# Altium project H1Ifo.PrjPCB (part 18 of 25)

## Sheet IfoEndX2.SchDoc: D1800185
size C; Engineer: Daniel Sigg; DocumentNumber: 6; Revision: 4; SheetNumber: 6; SheetTotal: 8
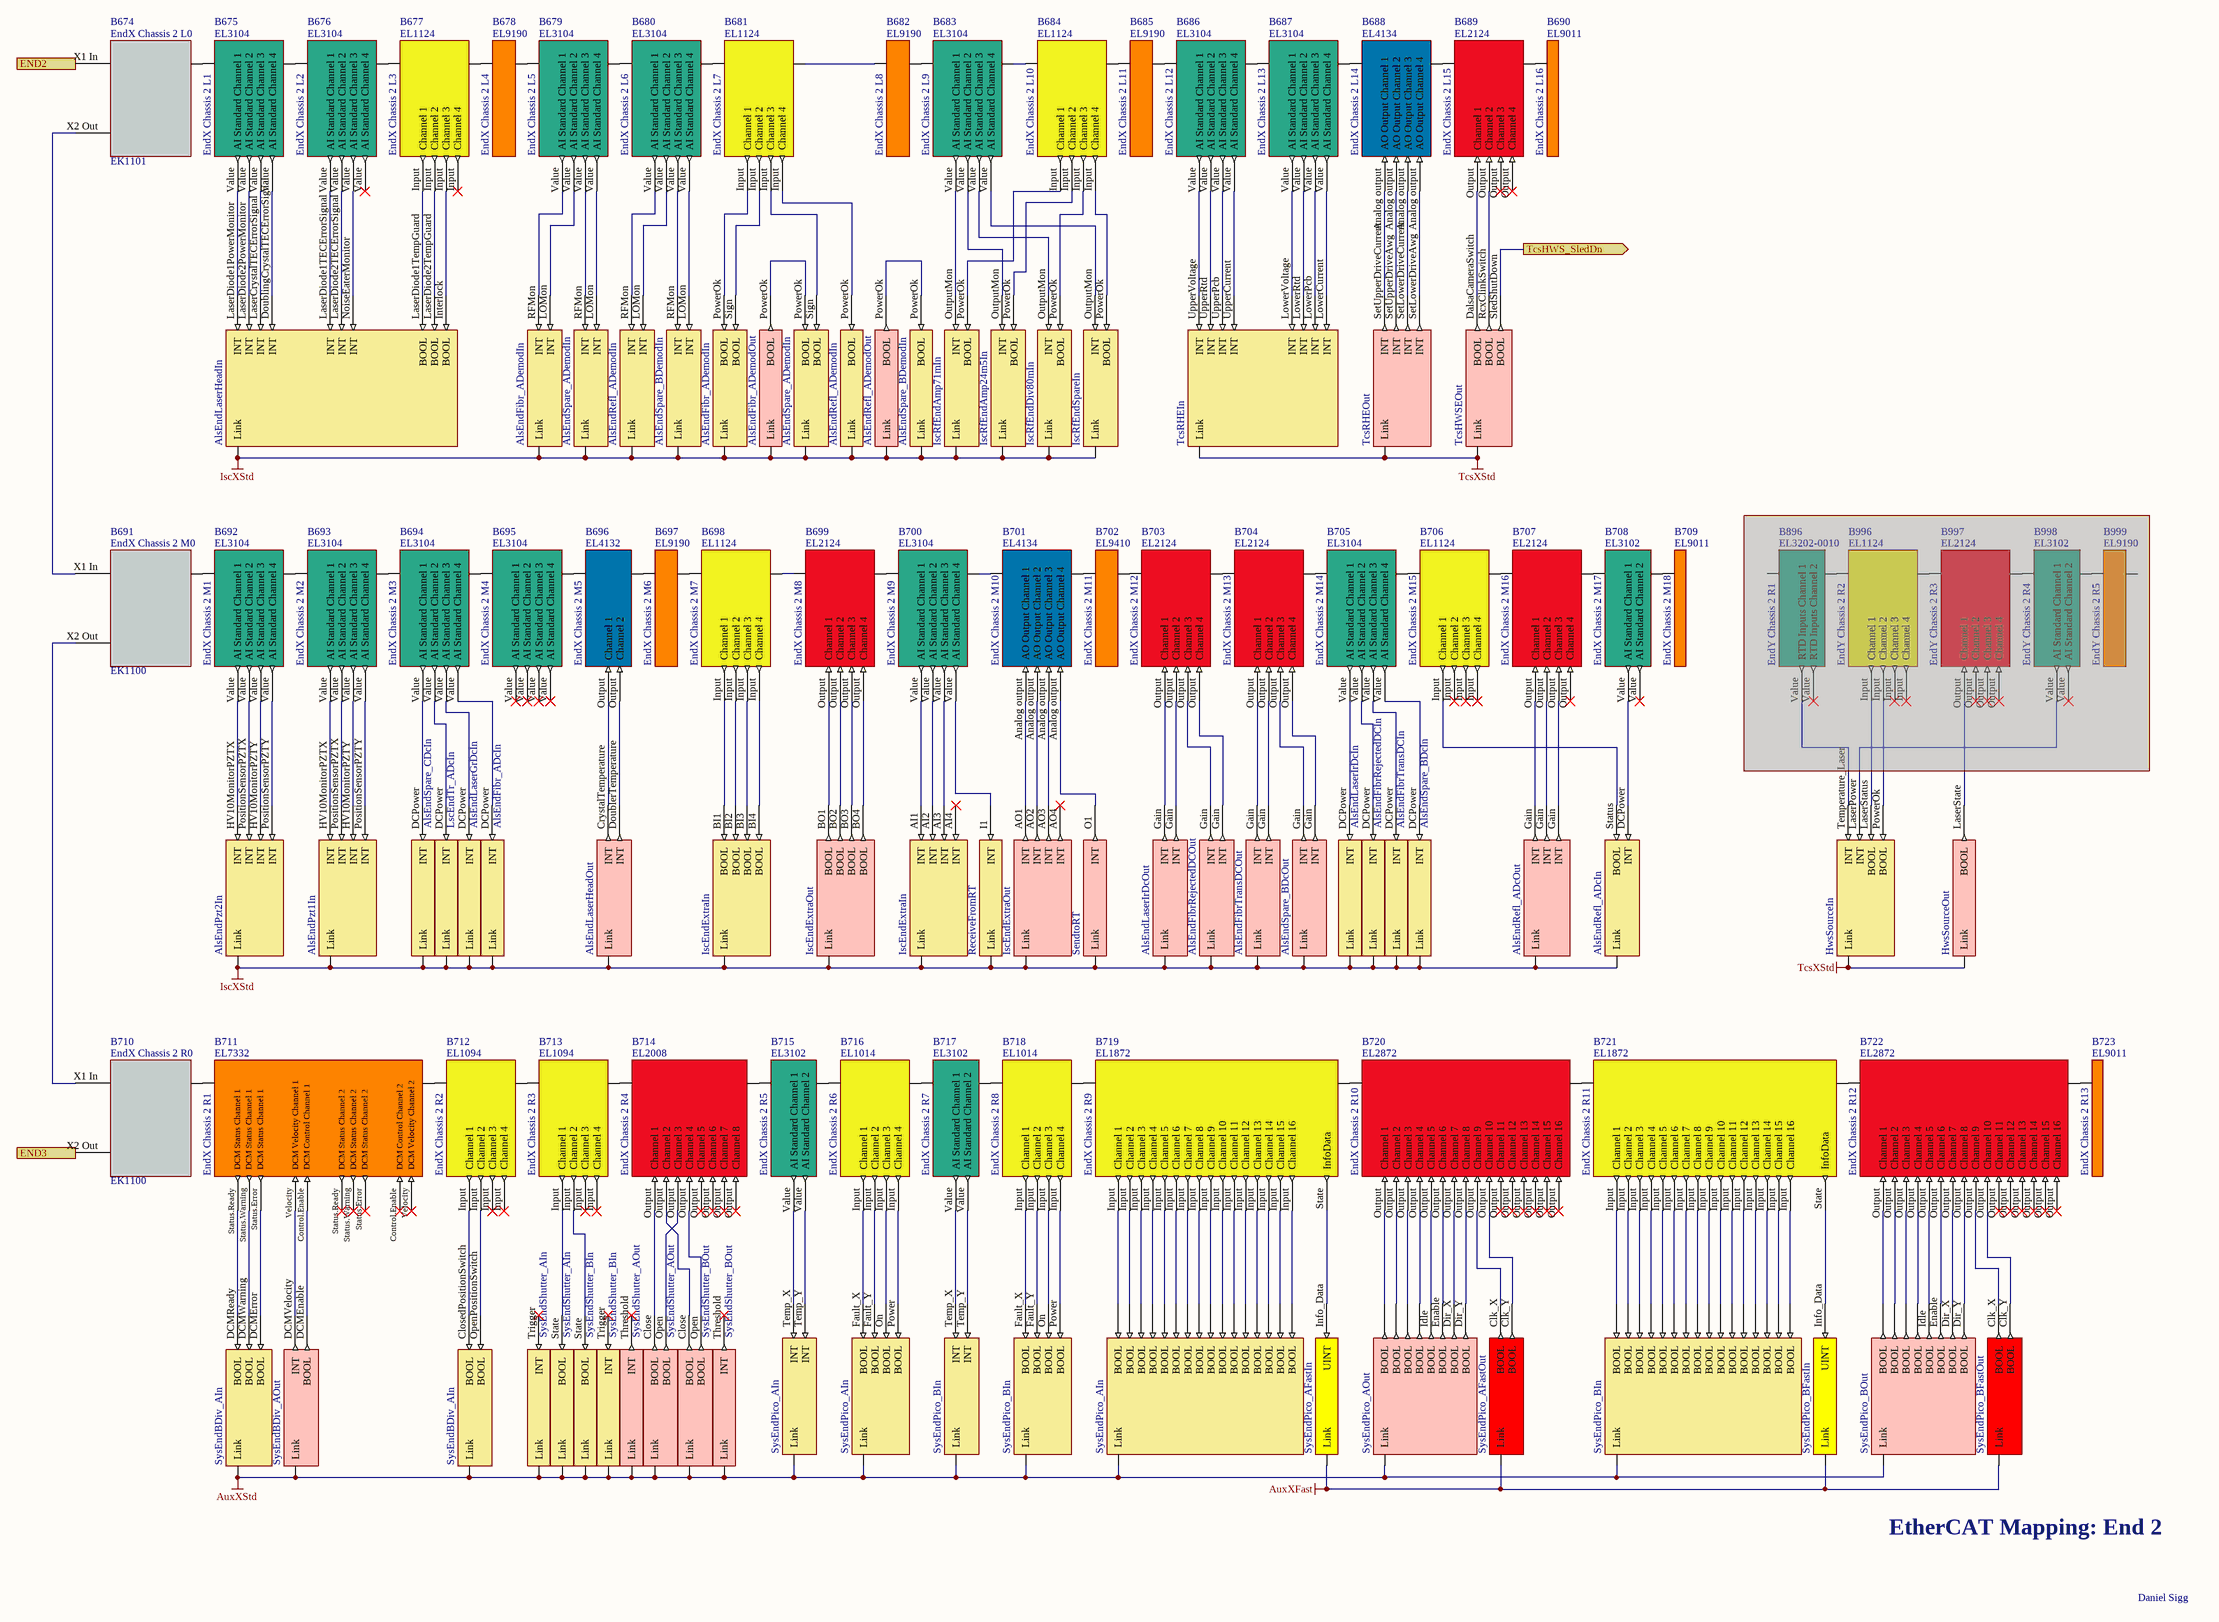
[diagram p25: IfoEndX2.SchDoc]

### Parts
(Parts that share a designator on the sheet are numbered #1, #2 ... from top to bottom, then left to right.)
B674  EndX Chassis 2 L0  Part Number: EK1101
B675  EndX Chassis 2 L1  Part Number: EL3104  (mechanical)
B676  EndX Chassis 2 L2  Part Number: EL3104  (mechanical)
B677  EndX Chassis 2 L3  Part Number: EL1124  (mechanical)
B678  EndX Chassis 2 L4  Part Number: EL9190  (mechanical)
B679  EndX Chassis 2 L5  Part Number: EL3104  (mechanical)
B680  EndX Chassis 2 L6  Part Number: EL3104  (mechanical)
B681  EndX Chassis 2 L7  Part Number: EL1124  (mechanical)
B682  EndX Chassis 2 L8  Part Number: EL9190  (mechanical)
B683  EndX Chassis 2 L9  Part Number: EL3104  (mechanical)
B684  EndX Chassis 2 L10  Part Number: EL1124  (mechanical)
B685  EndX Chassis 2 L11  Part Number: EL9190  (mechanical)
B686  EndX Chassis 2 L12  Part Number: EL3104  (mechanical)
B687  EndX Chassis 2 L13  Part Number: EL3104  (mechanical)
B688  EndX Chassis 2 L14  Part Number: EL4134  (mechanical)
B689  EndX Chassis 2 L15  Part Number: EL2124  (mechanical)
B690  EndX Chassis 2 L16  Part Number: EL9011  (mechanical)
B691  EndX Chassis 2 M0  Part Number: EK1100
B692  EndX Chassis 2 M1  Part Number: EL3104  (mechanical)
B693  EndX Chassis 2 M2  Part Number: EL3104  (mechanical)
B694  EndX Chassis 2 M3  Part Number: EL3104  (mechanical)
B695  EndX Chassis 2 M4  Part Number: EL3104  (mechanical)
B696  EndX Chassis 2 M5  Part Number: EL4132  (mechanical)
B697  EndX Chassis 2 M6  Part Number: EL9190  (mechanical)
B698  EndX Chassis 2 M7  Part Number: EL1124  (mechanical)
B699  EndX Chassis 2 M8  Part Number: EL2124  (mechanical)
B700  EndX Chassis 2 M9  Part Number: EL3104  (mechanical)
B701  EndX Chassis 2 M10  Part Number: EL4134  (mechanical)
B702  EndX Chassis 2 M11  Part Number: EL9410  (mechanical)
B703  EndX Chassis 2 M12  Part Number: EL2124  (mechanical)
B704  EndX Chassis 2 M13  Part Number: EL2124  (mechanical)
B705  EndX Chassis 2 M14  Part Number: EL3104  (mechanical)
B706  EndX Chassis 2 M15  Part Number: EL1124  (mechanical)
B707  EndX Chassis 2 M16  Part Number: EL2124  (mechanical)
B708  EndX Chassis 2 M17  Part Number: EL3102  (mechanical)
B709  EndX Chassis 2 M18  Part Number: EL9011  (mechanical)
B710  EndX Chassis 2 R0  Part Number: EK1100
B711  EndX Chassis 2 R1  Part Number: EL7332  (mechanical)
B712  EndX Chassis 2 R2  Part Number: EL1094  (mechanical)
B713  EndX Chassis 2 R3  Part Number: EL1094  (mechanical)
B714  EndX Chassis 2 R4  Part Number: EL2008  (mechanical)
B715  EndX Chassis 2 R5  Part Number: EL3102  (mechanical)
B716  EndX Chassis 2 R6  Part Number: EL1014  (mechanical)
B717  EndX Chassis 2 R7  Part Number: EL3102  (mechanical)
B718  EndX Chassis 2 R8  Part Number: EL1014  (mechanical)
B719  EndX Chassis 2 R9  Part Number: EL1872  (mechanical)
B720  EndX Chassis 2 R10  Part Number: EL2872  (mechanical)
B721  EndX Chassis 2 R11  Part Number: EL1872  (mechanical)
B722  EndX Chassis 2 R12  Part Number: EL2872  (mechanical)
B723  EndX Chassis 2 R13  Part Number: EL9011  (mechanical)
B896#1  EndY Chassis 2 R1  Part Number: EL3202-0010  (mechanical)  (masked out: inside a compile mask, not in the netlist)
B996#1  EndY Chassis 2 R2  Part Number: EL1124  (mechanical)  (masked out: inside a compile mask, not in the netlist)
B997#1  EndY Chassis 2 R3  Part Number: EL2124  (mechanical)  (masked out: inside a compile mask, not in the netlist)
B998#1  EndY Chassis 2 R4  Part Number: EL3102  (mechanical)  (masked out: inside a compile mask, not in the netlist)
B999#1  EndY Chassis 2 R5  Part Number: EL9190  (mechanical)  (masked out: inside a compile mask, not in the netlist)
V97  HwsSourceIn  (no BOM)
V98  HwsSourceOut  (no BOM)
V400  AlsEndFibr_ADemodOut  (no BOM)
V401  AlsEndRefl_ADemodOut  (no BOM)
V402  AlsEndFibr_ADemodIn  (parts A,B of 2)  (no BOM)
V403  AlsEndSpare_ADemodIn  (parts A,B of 2)  (no BOM)
V404  AlsEndRefl_ADemodIn  (parts A,B of 2)  (no BOM)
V405  AlsEndSpare_BDemodIn  (parts A,B of 2)  (no BOM)
V488  SysEndPico_AIn  (parts A,B,C of 3)  (no BOM)
V489  SysEndPico_BIn  (parts A,B,C of 3)  (no BOM)
V542  AlsEndLaserHeadIn  (no BOM)
V543  IscRfEndAmp71mIn  (no BOM)
V544  IscRfEndAmp24m5In  (no BOM)
V545  IscRfEndDiv80mIn  (no BOM)
V546  IscRfEndSpareIn  (no BOM)
V547  TcsRHEIn  (no BOM)
V548  TcsRHEOut  (no BOM)
V549  TcsHWSEOut  (no BOM)
V550  AlsEndPzt2In  (no BOM)
V551  AlsEndPzt1In  (no BOM)
V552  AlsEndSpare_CDcIn  (no BOM)
V553  LscEndTr_ADcIn  (no BOM)
V554  AlsEndLaserGrDcIn  (no BOM)
V555  AlsEndFibr_ADcIn  (no BOM)
V556  AlsEndLaserHeadOut  (part A of 2)  (no BOM)
V557  IscEndExtraIn  (parts A,B of 2)  (no BOM)
V558  IscEndExtraOut  (parts A,B of 2)  (no BOM)
V559  ReceiveFromRT  (no BOM)
V560  SendtoRT  (no BOM)
V561  AlsEndLaserIrDcOut  (no BOM)
V562  AlsEndFibrRejectedDCOut  (no BOM)
V563  AlsEndFibrTransDCOut  (no BOM)
V564  AlsEndSpare_BDcOut  (no BOM)
V565  AlsEndLaserIrDcIn  (no BOM)
V566  AlsEndFibrRejectedDCIn  (no BOM)
V569  AlsEndFibrTransDCIn  (no BOM)
V570  AlsEndSpare_BDcIn  (no BOM)
V571  AlsEndRefl_ADcOut  (no BOM)
V572  AlsEndRefl_ADcIn  (no BOM)
V573  SysEndPico_AFastIn  (no BOM)
V574  SysEndPico_AOut  (no BOM)
V575  SysEndPico_AFastOut  (no BOM)
V576  SysEndPico_BFastIn  (no BOM)
V577  SysEndPico_BOut  (no BOM)
V578  SysEndPico_BFastOut  (no BOM)
V579  SysEndBDiv_AIn  (parts A,B of 2)  (no BOM)
V580  SysEndBDiv_AOut  (no BOM)
V581  SysEndShutter_AIn  (parts A,B of 2)  (no BOM)
V582  SysEndShutter_BIn  (parts A,B of 2)  (no BOM)
V583  SysEndShutter_BOut  (parts A,B of 2)  (no BOM)
V721  SysEndShutter_AOut  (parts A,B of 2)  (no BOM)

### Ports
END2, END3, TcsHWS_SledDn (out)

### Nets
AuxXFast: V573.0(Link) V575.0(Link) V576.0(Link) V578.0(Link)
AuxXStd: V488.0(Link) V488.1(Link) V488.2(Link) V489.0(Link) V489.1(Link) V489.2(Link) V574.0(Link) V577.0(Link) V579.0(Link) V579.1(Link) V580.0(Link) V581.0(Link) V581.1(Link) V582.0(Link) V582.1(Link) V583.0(Link) V583.1(Link) V721.0(Link) V721.1(Link)
IscXStd: V400.?1(Link) V401.?1(Link) V402.0(Link) V402.1(Link) V403.0(Link) V403.1(Link) V404.0(Link) V404.1(Link) V405.0(Link) V405.1(Link) V542.0(Link) V543.?1(Link) V544.?1(Link) V545.?1(Link) V546.?1(Link) V550.0(Link) V551.0(Link) V552.1(Link) V553.1(Link) V554.1(Link) V555.1(Link) V556.0(Link) V557.0(Link) V557.1(Link) V558.0(Link) V558.1(Link) V559.1(Link) V560.0(Link) V561.0(Link) V562.0(Link) V563.0(Link) V564.0(Link) V565.1(Link) V566.1(Link) V569.1(Link) V570.1(Link) V571.0(Link) V572.1(Link)
TcsXStd: V97.1(Link) V98.0(Link) V547.0(Link) V548.0(Link) V549.0(Link)
NetB658_X2 Out: B674.X1_In(A) ; port END2
NetB674_Ebus: B674.Ebus(B) B675.Ebus(A)
NetB674_X2 Out: B674.X2_Out(C) B691.X1_In(A)
NetB675_Ebus: B675.Ebus(B) B676.Ebus(A)
NetB675_Value: B675.Value(AI_Standard_Channel_1) V542.LaserDiode1PowerMonitor(INT)
NetB675_Value: B675.Value(AI_Standard_Channel_2) V542.LaserDiode2PowerMonitor(INT)  [a separate net that carries the same name]
NetB675_Value: B675.Value(AI_Standard_Channel_3) V542.LaserCrystalTECErrorSignal(INT)  [a separate net that carries the same name]
NetB675_Value: B675.Value(AI_Standard_Channel_4) V542.DoublingCrystalTECErrorSignal(INT)  [a separate net that carries the same name]
NetB676_Ebus: B676.Ebus(B) B677.Ebus(A)
NetB676_Value: B676.Value(AI_Standard_Channel_1) V542.LaserDiode1TECErrorSignal(INT)
NetB676_Value: B676.Value(AI_Standard_Channel_2) V542.LaserDiode2TECErrorSignal(INT)  [a separate net that carries the same name]
NetB676_Value: B676.Value(AI_Standard_Channel_3) V542.NoiseEaterMonitor(INT)  [a separate net that carries the same name]
NetB677_Ebus: B677.Ebus(B) B678.Ebus(A)
NetB677_Input: B677.Input(Channel_1) V542.LaserDiode1TempGuard(BOOL)
NetB677_Input: B677.Input(Channel_2) V542.LaserDiode2TempGuard(BOOL)  [a separate net that carries the same name]
NetB677_Input: B677.Input(Channel_3) V542.Interlock(BOOL)  [a separate net that carries the same name]
NetB678_Ebus: B678.Ebus(B) B679.Ebus(A)
NetB679_Ebus: B679.Ebus(B) B680.Ebus(A)
NetB679_Value: B679.Value(AI_Standard_Channel_1) V402.RFMon(INT)
NetB679_Value: B679.Value(AI_Standard_Channel_2) V402.LOMon(INT)  [a separate net that carries the same name]
NetB679_Value: B679.Value(AI_Standard_Channel_3) V403.RFMon(INT)  [a separate net that carries the same name]
NetB679_Value: B679.Value(AI_Standard_Channel_4) V403.LOMon(INT)  [a separate net that carries the same name]
NetB680_Ebus: B680.Ebus(B) B681.Ebus(A)
NetB680_Value: B680.Value(AI_Standard_Channel_1) V404.RFMon(INT)
NetB680_Value: B680.Value(AI_Standard_Channel_2) V404.LOMon(INT)  [a separate net that carries the same name]
NetB680_Value: B680.Value(AI_Standard_Channel_3) V405.RFMon(INT)  [a separate net that carries the same name]
NetB680_Value: B680.Value(AI_Standard_Channel_4) V405.LOMon(INT)  [a separate net that carries the same name]
NetB681_Ebus: B681.Ebus(B) B682.Ebus(A)
NetB681_Input: B681.Input(Channel_1) V402.PowerOk(BOOL)
NetB681_Input: B681.Input(Channel_2) V402.Sign(BOOL)  [a separate net that carries the same name]
NetB681_Input: B681.Input(Channel_3) V403.Sign(BOOL)  [a separate net that carries the same name]
NetB681_Input: B681.Input(Channel_4) V404.PowerOk(BOOL)  [a separate net that carries the same name]
NetB682_Ebus: B682.Ebus(B) B683.Ebus(A)
NetB683_Ebus: B683.Ebus(B) B684.Ebus(A)
NetB683_Value: B683.Value(AI_Standard_Channel_1) V543.OutputMon(INT)
NetB683_Value: B683.Value(AI_Standard_Channel_2) V544.OutputMon(INT)  [a separate net that carries the same name]
NetB683_Value: B683.Value(AI_Standard_Channel_3) V545.OutputMon(INT)  [a separate net that carries the same name]
NetB683_Value: B683.Value(AI_Standard_Channel_4) V546.OutputMon(INT)  [a separate net that carries the same name]
NetB684_Ebus: B684.Ebus(B) B685.Ebus(A)
NetB684_Input: B684.Input(Channel_1) V543.PowerOk(BOOL)
NetB684_Input: B684.Input(Channel_2) V544.PowerOk(BOOL)  [a separate net that carries the same name]
NetB684_Input: B684.Input(Channel_3) V545.PowerOk(BOOL)  [a separate net that carries the same name]
NetB684_Input: B684.Input(Channel_4) V546.PowerOk(BOOL)  [a separate net that carries the same name]
NetB685_Ebus: B685.Ebus(B) B686.Ebus(A)
NetB686_Ebus: B686.Ebus(B) B687.Ebus(A)
NetB686_Value: B686.Value(AI_Standard_Channel_1) V547.UpperVoltage(INT)
NetB686_Value: B686.Value(AI_Standard_Channel_2) V547.UpperRtd(INT)  [a separate net that carries the same name]
NetB686_Value: B686.Value(AI_Standard_Channel_3) V547.UpperPcb(INT)  [a separate net that carries the same name]
NetB686_Value: B686.Value(AI_Standard_Channel_4) V547.UpperCurrent(INT)  [a separate net that carries the same name]
NetB687_Ebus: B687.Ebus(B) B688.Ebus(A)
NetB687_Value: B687.Value(AI_Standard_Channel_1) V547.LowerVoltage(INT)
NetB687_Value: B687.Value(AI_Standard_Channel_2) V547.LowerRtd(INT)  [a separate net that carries the same name]
NetB687_Value: B687.Value(AI_Standard_Channel_3) V547.LowerPcb(INT)  [a separate net that carries the same name]
NetB687_Value: B687.Value(AI_Standard_Channel_4) V547.LowerCurrent(INT)  [a separate net that carries the same name]
NetB688_Analog output: B688.Analog_output(AO_Output_Channel_1) V548.SetUpperDriveCurrent(INT)
NetB688_Analog output: B688.Analog_output(AO_Output_Channel_2) V548.SetUpperDriveAwg(INT)  [a separate net that carries the same name]
NetB688_Analog output: B688.Analog_output(AO_Output_Channel_3) V548.SetLowerDriveCurrent(INT)  [a separate net that carries the same name]
NetB688_Analog output: B688.Analog_output(AO_Output_Channel_4) V548.SetLowerDriveAwg(INT)  [a separate net that carries the same name]
NetB688_Ebus: B688.Ebus(B) B689.Ebus(A)
NetB689_Ebus: B689.Ebus(B) B690.Ebus(A)
NetB689_Output: B689.Output(Channel_1) V549.DalsaCameraSwitch(BOOL)
NetB689_Output: B689.Output(Channel_2) V549.RcxClinkSwitch(BOOL)  [a separate net that carries the same name]
NetB691_Ebus: B691.Ebus(B) B692.Ebus(A)
NetB691_X2 Out: B691.X2_Out(C) B710.X1_In(A)
NetB692_Ebus: B692.Ebus(B) B693.Ebus(A)
NetB692_Value: B692.Value(AI_Standard_Channel_1) V550.HV10MonitorPZTX(INT)
NetB692_Value: B692.Value(AI_Standard_Channel_2) V550.PositionSensorPZTX(INT)  [a separate net that carries the same name]
NetB692_Value: B692.Value(AI_Standard_Channel_3) V550.HV10MonitorPZTY(INT)  [a separate net that carries the same name]
NetB692_Value: B692.Value(AI_Standard_Channel_4) V550.PositionSensorPZTY(INT)  [a separate net that carries the same name]
NetB693_Ebus: B693.Ebus(B) B694.Ebus(A)
NetB693_Value: B693.Value(AI_Standard_Channel_1) V551.HV10MonitorPZTX(INT)
NetB693_Value: B693.Value(AI_Standard_Channel_2) V551.PositionSensorPZTX(INT)  [a separate net that carries the same name]
NetB693_Value: B693.Value(AI_Standard_Channel_3) V551.HV10MonitorPZTY(INT)  [a separate net that carries the same name]
NetB693_Value: B693.Value(AI_Standard_Channel_4) V551.PositionSensorPZTY(INT)  [a separate net that carries the same name]
NetB694_Ebus: B694.Ebus(B) B695.Ebus(A)
NetB694_Value: B694.Value(AI_Standard_Channel_1) V552.DCPower(INT)
NetB694_Value: B694.Value(AI_Standard_Channel_2) V553.DCPower(INT)  [a separate net that carries the same name]
NetB694_Value: B694.Value(AI_Standard_Channel_3) V554.DCPower(INT)  [a separate net that carries the same name]
NetB694_Value: B694.Value(AI_Standard_Channel_4) V555.DCPower(INT)  [a separate net that carries the same name]
NetB695_Ebus: B695.Ebus(B) B696.Ebus(A)
NetB696_Ebus: B696.Ebus(B) B697.Ebus(A)
NetB696_Output: B696.Output(Channel_1) V556.CrystalTemperature(INT)
NetB696_Output: B696.Output(Channel_2) V556.DoublerTemperature(INT)  [a separate net that carries the same name]
NetB697_Ebus: B697.Ebus(B) B698.Ebus(A)
NetB698_Ebus: B698.Ebus(B) B699.Ebus(A)
NetB698_Input: B698.Input(Channel_1) V557.BI1(BOOL)
NetB698_Input: B698.Input(Channel_2) V557.BI2(BOOL)  [a separate net that carries the same name]
NetB698_Input: B698.Input(Channel_3) V557.BI3(BOOL)  [a separate net that carries the same name]
NetB698_Input: B698.Input(Channel_4) V557.BI4(BOOL)  [a separate net that carries the same name]
NetB699_Ebus: B699.Ebus(B) B700.Ebus(A)
NetB699_Output: B699.Output(Channel_1) V558.BO1(BOOL)
NetB699_Output: B699.Output(Channel_2) V558.BO2(BOOL)  [a separate net that carries the same name]
NetB699_Output: B699.Output(Channel_3) V558.BO3(BOOL)  [a separate net that carries the same name]
NetB699_Output: B699.Output(Channel_4) V558.BO4(BOOL)  [a separate net that carries the same name]
NetB700_Ebus: B700.Ebus(B) B701.Ebus(A)
NetB700_Value: B700.Value(AI_Standard_Channel_1) V557.AI1(INT)
NetB700_Value: B700.Value(AI_Standard_Channel_2) V557.AI2(INT)  [a separate net that carries the same name]
NetB700_Value: B700.Value(AI_Standard_Channel_3) V557.AI3(INT)  [a separate net that carries the same name]
NetB700_Value: B700.Value(AI_Standard_Channel_4) V559.I1(INT)  [a separate net that carries the same name]
NetB701_Analog output: B701.Analog_output(AO_Output_Channel_1) V558.AO1(INT)
NetB701_Analog output: B701.Analog_output(AO_Output_Channel_2) V558.AO2(INT)  [a separate net that carries the same name]
NetB701_Analog output: B701.Analog_output(AO_Output_Channel_3) V558.AO3(INT)  [a separate net that carries the same name]
NetB701_Analog output: B701.Analog_output(AO_Output_Channel_4) V560.O1(INT)  [a separate net that carries the same name]
NetB701_Ebus: B701.Ebus(B) B702.Ebus(A)
NetB702_Ebus: B702.Ebus(B) B703.Ebus(A)
NetB703_Ebus: B703.Ebus(B) B704.Ebus(A)
NetB703_Output: B703.Output(Channel_1) V561.Gain(INT)
NetB703_Output: B703.Output(Channel_2) V561.Gain(INT)  [a separate net that carries the same name]
NetB703_Output: B703.Output(Channel_3) V562.Gain(INT)  [a separate net that carries the same name]
NetB703_Output: B703.Output(Channel_4) V562.Gain(INT)  [a separate net that carries the same name]
NetB704_Ebus: B704.Ebus(B) B705.Ebus(A)
NetB704_Output: B704.Output(Channel_1) V563.Gain(INT)
NetB704_Output: B704.Output(Channel_2) V563.Gain(INT)  [a separate net that carries the same name]
NetB704_Output: B704.Output(Channel_3) V564.Gain(INT)  [a separate net that carries the same name]
NetB704_Output: B704.Output(Channel_4) V564.Gain(INT)  [a separate net that carries the same name]
NetB705_Ebus: B705.Ebus(B) B706.Ebus(A)
NetB705_Value: B705.Value(AI_Standard_Channel_1) V565.DCPower(INT)
NetB705_Value: B705.Value(AI_Standard_Channel_2) V566.DCPower(INT)  [a separate net that carries the same name]
NetB705_Value: B705.Value(AI_Standard_Channel_3) V569.DCPower(INT)  [a separate net that carries the same name]
NetB705_Value: B705.Value(AI_Standard_Channel_4) V570.DCPower(INT)  [a separate net that carries the same name]
NetB706_Ebus: B706.Ebus(B) B707.Ebus(A)
NetB706_Input: B706.Input(Channel_1) V572.Status(BOOL)
NetB707_Ebus: B707.Ebus(B) B708.Ebus(A)
NetB707_Output: B707.Output(Channel_1) V571.Gain(INT)
NetB707_Output: B707.Output(Channel_2) V571.Gain(INT)  [a separate net that carries the same name]
NetB707_Output: B707.Output(Channel_3) V571.Gain(INT)  [a separate net that carries the same name]
NetB708_Ebus: B708.Ebus(B) B709.Ebus(A)
NetB708_Value: B708.Value(AI_Standard_Channel_1) V572.DCPower(INT)
NetB710_Ebus: B710.Ebus(B) B711.Ebus(A)
NetB710_X2 Out: B710.X2_Out(C) ; port END3
NetB711_Control.Enable: B711.Control.Enable(DCM_Control_Channel_1) V580.DCMEnable(BOOL)
NetB711_Ebus: B711.Ebus(B) B712.Ebus(A)
NetB711_Status.Error: B711.Status.Error(DCM_Status_Channel_1) V579.DCMError(BOOL)
NetB711_Status.Ready: B711.Status.Ready(DCM_Status_Channel_1) V579.DCMReady(BOOL)
NetB711_Status.Warning: B711.Status.Warning(DCM_Status_Channel_1) V579.DCMWarning(BOOL)
NetB711_Velocity: B711.Velocity(DCM_Velocity_Channel_1) V580.DCMVelocity(INT)
NetB712_Ebus: B712.Ebus(B) B713.Ebus(A)
NetB712_Input: B712.Input(Channel_1) V579.ClosedPositionSwitch(BOOL)
NetB712_Input: B712.Input(Channel_2) V579.OpenPositionSwitch(BOOL)  [a separate net that carries the same name]
NetB713_Ebus: B713.Ebus(B) B714.Ebus(A)
NetB713_Input: B713.Input(Channel_1) V581.State(BOOL)
NetB713_Input: B713.Input(Channel_2) V582.State(BOOL)  [a separate net that carries the same name]
NetB714_Ebus: B714.Ebus(B) B715.Ebus(A)
NetB714_Output: B714.Output(Channel_1) V721.Close(BOOL)
NetB714_Output: B714.Output(Channel_2) V583.Close(BOOL)  [a separate net that carries the same name]
NetB714_Output: B714.Output(Channel_3) V721.Open(BOOL)  [a separate net that carries the same name]
NetB714_Output: B714.Output(Channel_4) V583.Open(BOOL)  [a separate net that carries the same name]
NetB715_Ebus: B715.Ebus(B) B716.Ebus(A)
NetB715_Value: B715.Value(AI_Standard_Channel_1) V488.Temp_X(INT)
NetB715_Value: B715.Value(AI_Standard_Channel_2) V488.Temp_Y(INT)  [a separate net that carries the same name]
NetB716_Ebus: B716.Ebus(B) B717.Ebus(A)
NetB716_Input: B716.Input(Channel_1) V488.Fault_X(BOOL)
NetB716_Input: B716.Input(Channel_2) V488.Fault_Y(BOOL)  [a separate net that carries the same name]
NetB716_Input: B716.Input(Channel_3) V488.On(BOOL)  [a separate net that carries the same name]
NetB716_Input: B716.Input(Channel_4) V488.Power(BOOL)  [a separate net that carries the same name]
NetB717_Ebus: B717.Ebus(B) B718.Ebus(A)
NetB717_Value: B717.Value(AI_Standard_Channel_1) V489.Temp_X(INT)
NetB717_Value: B717.Value(AI_Standard_Channel_2) V489.Temp_Y(INT)  [a separate net that carries the same name]
NetB718_Ebus: B718.Ebus(B) B719.Ebus(A)
NetB718_Input: B718.Input(Channel_1) V489.Fault_X(BOOL)
NetB718_Input: B718.Input(Channel_2) V489.Fault_Y(BOOL)  [a separate net that carries the same name]
NetB718_Input: B718.Input(Channel_3) V489.On(BOOL)  [a separate net that carries the same name]
NetB718_Input: B718.Input(Channel_4) V489.Power(BOOL)  [a separate net that carries the same name]
NetB719_Ebus: B719.Ebus(B) B720.Ebus(A)
NetB719_Input: B719.Input(Channel_1) V488.MotorX1(BOOL)
NetB719_Input: B719.Input(Channel_2) V488.MotorX2(BOOL)  [a separate net that carries the same name]
NetB719_Input: B719.Input(Channel_3) V488.MotorX3(BOOL)  [a separate net that carries the same name]
NetB719_Input: B719.Input(Channel_4) V488.MotorX4(BOOL)  [a separate net that carries the same name]
NetB719_Input: B719.Input(Channel_5) V488.MotorX5(BOOL)  [a separate net that carries the same name]
NetB719_Input: B719.Input(Channel_6) V488.MotorX6(BOOL)  [a separate net that carries the same name]
NetB719_Input: B719.Input(Channel_7) V488.MotorX7(BOOL)  [a separate net that carries the same name]
NetB719_Input: B719.Input(Channel_8) V488.MotorX8(BOOL)  [a separate net that carries the same name]
NetB719_Input: B719.Input(Channel_9) V488.MotorY1(BOOL)  [a separate net that carries the same name]
NetB719_Input: B719.Input(Channel_10) V488.MotorY2(BOOL)  [a separate net that carries the same name]
NetB719_Input: B719.Input(Channel_11) V488.MotorY3(BOOL)  [a separate net that carries the same name]
NetB719_Input: B719.Input(Channel_12) V488.MotorY4(BOOL)  [a separate net that carries the same name]
NetB719_Input: B719.Input(Channel_13) V488.MotorY5(BOOL)  [a separate net that carries the same name]
NetB719_Input: B719.Input(Channel_14) V488.MotorY6(BOOL)  [a separate net that carries the same name]
NetB719_Input: B719.Input(Channel_15) V488.MotorY7(BOOL)  [a separate net that carries the same name]
NetB719_Input: B719.Input(Channel_16) V488.MotorY8(BOOL)  [a separate net that carries the same name]
NetB719_State: B719.State(InfoData) V573.Info_Data(UINT)
NetB720_Ebus: B720.Ebus(B) B721.Ebus(A)
NetB720_Output: B720.Output(Channel_1) V574.MOTOR3(BOOL)
NetB720_Output: B720.Output(Channel_2) V574.MOTOR2(BOOL)  [a separate net that carries the same name]
NetB720_Output: B720.Output(Channel_3) V574.MOTOR1(BOOL)  [a separate net that carries the same name]
NetB720_Output: B720.Output(Channel_4) V574.MOTOR4(BOOL)  [a separate net that carries the same name]
NetB720_Output: B720.Output(Channel_5) V574.Idle(BOOL)  [a separate net that carries the same name]
NetB720_Output: B720.Output(Channel_6) V574.Enable(BOOL)  [a separate net that carries the same name]
NetB720_Output: B720.Output(Channel_7) V574.Dir_X(BOOL)  [a separate net that carries the same name]
NetB720_Output: B720.Output(Channel_8) V574.Dir_Y(BOOL)  [a separate net that carries the same name]
NetB720_Output: B720.Output(Channel_9) V575.Clk_X(BOOL)  [a separate net that carries the same name]
NetB720_Output: B720.Output(Channel_10) V575.Clk_Y(BOOL)  [a separate net that carries the same name]
NetB721_Ebus: B721.Ebus(B) B722.Ebus(A)
NetB721_Input: B721.Input(Channel_1) V489.MotorX1(BOOL)
NetB721_Input: B721.Input(Channel_2) V489.MotorX2(BOOL)  [a separate net that carries the same name]
NetB721_Input: B721.Input(Channel_3) V489.MotorX3(BOOL)  [a separate net that carries the same name]
NetB721_Input: B721.Input(Channel_4) V489.MotorX4(BOOL)  [a separate net that carries the same name]
NetB721_Input: B721.Input(Channel_5) V489.MotorX5(BOOL)  [a separate net that carries the same name]
NetB721_Input: B721.Input(Channel_6) V489.MotorX6(BOOL)  [a separate net that carries the same name]
NetB721_Input: B721.Input(Channel_7) V489.MotorX7(BOOL)  [a separate net that carries the same name]
NetB721_Input: B721.Input(Channel_8) V489.MotorX8(BOOL)  [a separate net that carries the same name]
NetB721_Input: B721.Input(Channel_9) V489.MotorY1(BOOL)  [a separate net that carries the same name]
NetB721_Input: B721.Input(Channel_10) V489.MotorY2(BOOL)  [a separate net that carries the same name]
NetB721_Input: B721.Input(Channel_11) V489.MotorY3(BOOL)  [a separate net that carries the same name]
NetB721_Input: B721.Input(Channel_12) V489.MotorY4(BOOL)  [a separate net that carries the same name]
NetB721_Input: B721.Input(Channel_13) V489.MotorY5(BOOL)  [a separate net that carries the same name]
NetB721_Input: B721.Input(Channel_14) V489.MotorY6(BOOL)  [a separate net that carries the same name]
NetB721_Input: B721.Input(Channel_15) V489.MotorY7(BOOL)  [a separate net that carries the same name]
NetB721_Input: B721.Input(Channel_16) V489.MotorY8(BOOL)  [a separate net that carries the same name]
NetB721_State: B721.State(InfoData) V576.Info_Data(UINT)
NetB722_Ebus: B722.Ebus(B) B723.Ebus(A)
NetB722_Output: B722.Output(Channel_1) V577.MOTOR3(BOOL)
NetB722_Output: B722.Output(Channel_2) V577.MOTOR2(BOOL)  [a separate net that carries the same name]
NetB722_Output: B722.Output(Channel_3) V577.MOTOR1(BOOL)  [a separate net that carries the same name]
NetB722_Output: B722.Output(Channel_4) V577.MOTOR4(BOOL)  [a separate net that carries the same name]
NetB722_Output: B722.Output(Channel_5) V577.Idle(BOOL)  [a separate net that carries the same name]
NetB722_Output: B722.Output(Channel_6) V577.Enable(BOOL)  [a separate net that carries the same name]
NetB722_Output: B722.Output(Channel_7) V577.Dir_X(BOOL)  [a separate net that carries the same name]
NetB722_Output: B722.Output(Channel_8) V577.Dir_Y(BOOL)  [a separate net that carries the same name]
NetB722_Output: B722.Output(Channel_9) V578.Clk_X(BOOL)  [a separate net that carries the same name]
NetB722_Output: B722.Output(Channel_10) V578.Clk_Y(BOOL)  [a separate net that carries the same name]
NetB738_Output: V549.SledShutDown(BOOL) ; port TcsHWS_SledDn
NetV400_PowerOk: V400.PowerOk(BOOL) V403.PowerOk(BOOL)
NetV401_PowerOk: V401.PowerOk(BOOL) V405.PowerOk(BOOL)

Not connected (* = marked no-connect by the designer): B695 Value(AI_Standard_Channel_1)*; V97 LaserPower(INT) LaserStatus(BOOL) PowerOk(BOOL) Temperature_Laser(INT); V98 LaserState(BOOL); V557 AI4(INT)*; V558 AO4(INT)*; V581 Trigger(INT)*; V582 Trigger(INT)*; V583 Threshold(INT)*; V721 Threshold(INT)*

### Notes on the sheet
- EtherCAT Mapping: End 2
- Daniel Sigg

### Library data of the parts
B674 = CouplerEK1101: EtherCAT Coupler; Rail: Left; BoxNextB: ALYINYRC; BoxNextC: TQNAFHKI; BoxPrev: ADQIHKND; PortPrevFull: 1045/C; PortPrevShort: C 'X2 Out'; Fullname: TIID^End X (EtherCAT)^EndX Link L0 (EK1501-0010)^EndX Link L6 (EK1521)^EndX Chassis 2 L0 (EK1101); BoxPorts: Junction; BoxAddr: 1058; Disabled: False
B675 = TerminalEL3104: EtherCAT Terminal EL3104 4-chn Analog Input; Rail: Left; BoxNextB: XBDNXVUK; BoxPrev: YKLANJOD; PortPrevFull: 1058/B; PortPrevShort: B; Fullname: TIID^End X (EtherCAT)^EndX Link L0 (EK1501-0010)^EndX Link L6 (EK1521)^EndX Chassis 2 L0 (EK1101)^EndX Chassis 2 L1 (EL3104); BoxAddr: 1059; Disabled: False
B676 = TerminalEL3104: EtherCAT Terminal EL3104 4-chn Analog Input; Rail: Left; BoxNextB: NEDEOYOK; BoxPrev: ALYINYRC; PortPrevFull: 1059/B; PortPrevShort: B; Fullname: TIID^End X (EtherCAT)^EndX Link L0 (EK1501-0010)^EndX Link L6 (EK1521)^EndX Chassis 2 L0 (EK1101)^EndX Chassis 2 L2 (EL3104); BoxAddr: 1060; Disabled: False
B677 = TerminalEL1124: EtherCAT Terminal EL1124 4-chn Digital Input; Rail: Left; BoxNextB: OJIDXIQW; BoxPrev: XBDNXVUK; PortPrevFull: 1060/B; PortPrevShort: B; Fullname: TIID^End X (EtherCAT)^EndX Link L0 (EK1501-0010)^EndX Link L6 (EK1521)^EndX Chassis 2 L0 (EK1101)^EndX Chassis 2 L3 (EL1124); BoxAddr: 1061; Disabled: False
B678 = TerminalEL9190: EtherCAT Terminal EL9190 Supply; BoxType: TerminalPassive; Rail: Left; BoxNextB: KPJLNEWT; BoxPrev: NEDEOYOK; PortPrevShort: B; Fullname: TIID^End X (EtherCAT)^EndX Link L0 (EK1501-0010)^EndX Link L6 (EK1521)^EndX Chassis 2 L0 (EK1101)^EndX Chassis 2 L4 (EL9190); Disabled: False
B679 = TerminalEL3104: EtherCAT Terminal EL3104 4-chn Analog Input; Rail: Left; BoxNextB: UBLIECNB; BoxPrev: OJIDXIQW; PortPrevFull: 1061/B; PortPrevShort: B; Fullname: TIID^End X (EtherCAT)^EndX Link L0 (EK1501-0010)^EndX Link L6 (EK1521)^EndX Chassis 2 L0 (EK1101)^EndX Chassis 2 L5 (EL3104); BoxAddr: 1062; Disabled: False
B680 = TerminalEL3104: EtherCAT Terminal EL3104 4-chn Analog Input; Rail: Left; BoxNextB: PHOILPND; BoxPrev: KPJLNEWT; PortPrevFull: 1062/B; PortPrevShort: B; Fullname: TIID^End X (EtherCAT)^EndX Link L0 (EK1501-0010)^EndX Link L6 (EK1521)^EndX Chassis 2 L0 (EK1101)^EndX Chassis 2 L6 (EL3104); BoxAddr: 1063; Disabled: False
B681 = TerminalEL1124: EtherCAT Terminal EL1124 4-chn Digital Input; Rail: Left; BoxNextB: DXDUCRMN; BoxPrev: UBLIECNB; PortPrevFull: 1063/B; PortPrevShort: B; Fullname: TIID^End X (EtherCAT)^EndX Link L0 (EK1501-0010)^EndX Link L6 (EK1521)^EndX Chassis 2 L0 (EK1101)^EndX Chassis 2 L7 (EL1124); BoxAddr: 1064; Disabled: False
B682 = TerminalEL9190: EtherCAT Terminal EL9190 Supply; BoxType: TerminalPassive; Rail: Left; BoxNextB: DSUQFQTB; BoxPrev: PHOILPND; PortPrevShort: B; Fullname: TIID^End X (EtherCAT)^EndX Link L0 (EK1501-0010)^EndX Link L6 (EK1521)^EndX Chassis 2 L0 (EK1101)^EndX Chassis 2 L8 (EL9190); Disabled: False
B683 = TerminalEL3104: EtherCAT Terminal EL3104 4-chn Analog Input; Rail: Left; BoxNextB: URCHLECG; BoxPrev: DXDUCRMN; PortPrevFull: 1064/B; PortPrevShort: B; Fullname: TIID^End X (EtherCAT)^EndX Link L0 (EK1501-0010)^EndX Link L6 (EK1521)^EndX Chassis 2 L0 (EK1101)^EndX Chassis 2 L9 (EL3104); BoxAddr: 1065; Disabled: False
B684 = TerminalEL1124: EtherCAT Terminal EL1124 4-chn Digital Input; Rail: Left; BoxNextB: PVOGEVNQ; BoxPrev: DSUQFQTB; PortPrevFull: 1065/B; PortPrevShort: B; Fullname: TIID^End X (EtherCAT)^EndX Link L0 (EK1501-0010)^EndX Link L6 (EK1521)^EndX Chassis 2 L0 (EK1101)^EndX Chassis 2 L10 (EL1124); BoxAddr: 1066; Disabled: False
B685 = TerminalEL9190: EtherCAT Terminal EL9190 Supply; BoxType: TerminalPassive; Rail: Left; BoxNextB: FLGHSIAX; BoxPrev: URCHLECG; PortPrevShort: B; Fullname: TIID^End X (EtherCAT)^EndX Link L0 (EK1501-0010)^EndX Link L6 (EK1521)^EndX Chassis 2 L0 (EK1101)^EndX Chassis 2 L11 (EL9190); Disabled: False
B686 = TerminalEL3104: EtherCAT Terminal EL3104 4-chn Analog Input; Rail: Left; BoxNextB: LXSMSKPU; BoxPrev: PVOGEVNQ; PortPrevFull: 1066/B; PortPrevShort: B; Fullname: TIID^End X (EtherCAT)^EndX Link L0 (EK1501-0010)^EndX Link L6 (EK1521)^EndX Chassis 2 L0 (EK1101)^EndX Chassis 2 L12 (EL3104); BoxAddr: 1067; Disabled: False
B687 = TerminalEL3104: EtherCAT Terminal EL3104 4-chn Analog Input; Rail: Left; BoxNextB: LJYHOCUG; BoxPrev: FLGHSIAX; PortPrevFull: 1067/B; PortPrevShort: B; Fullname: TIID^End X (EtherCAT)^EndX Link L0 (EK1501-0010)^EndX Link L6 (EK1521)^EndX Chassis 2 L0 (EK1101)^EndX Chassis 2 L13 (EL3104); BoxAddr: 1068; Disabled: False
B688 = TerminalEL4134: EtherCAT Terminal EL4134 4-chn Analog Ouput; Rail: Left; BoxNextB: TTHPRELV; BoxPrev: LXSMSKPU; PortPrevFull: 1068/B; PortPrevShort: B; Fullname: TIID^End X (EtherCAT)^EndX Link L0 (EK1501-0010)^EndX Link L6 (EK1521)^EndX Chassis 2 L0 (EK1101)^EndX Chassis 2 L14 (EL4134); BoxAddr: 1069; Disabled: False
B689 = TerminalEL2124: EtherCAT Terminal EL2124 4-chn Digital Ouput; Rail: Left; BoxNextB: HCOXLUGR; BoxPrev: LJYHOCUG; PortPrevFull: 1069/B; PortPrevShort: B; Fullname: TIID^End X (EtherCAT)^EndX Link L0 (EK1501-0010)^EndX Link L6 (EK1521)^EndX Chassis 2 L0 (EK1101)^EndX Chassis 2 L15 (EL2124); BoxAddr: 1070; Disabled: False
B690 = TerminalEL9011: EtherCAT Terminal EL9011 End; BoxType: TerminalPassive; Rail: Left; BoxPrev: TTHPRELV; PortPrevShort: B; Fullname: TIID^End X (EtherCAT)^EndX Link L0 (EK1501-0010)^EndX Link L6 (EK1521)^EndX Chassis 2 L0 (EK1101)^EndX Chassis 2 L16 (EL9011); Disabled: False
B691 = CouplerEK1100: EtherCAT Coupler; Rail: Middle; BoxNextB: BIXFLARP; BoxNextC: WVQJRASG; BoxPrev: YKLANJOD; PortPrevFull: 1058/C; PortPrevShort: C 'X2 Out'; Fullname: TIID^End X (EtherCAT)^EndX Link L0 (EK1501-0010)^EndX Link L6 (EK1521)^EndX Chassis 2 M0 (EK1100); BoxPorts: Junction; BoxAddr: 1071; Disabled: False
B692 = TerminalEL3104: EtherCAT Terminal EL3104 4-chn Analog Input; Rail: Middle; BoxNextB: NWYIOJYV; BoxPrev: TQNAFHKI; PortPrevFull: 1071/B; PortPrevShort: B; Fullname: TIID^End X (EtherCAT)^EndX Link L0 (EK1501-0010)^EndX Link L6 (EK1521)^EndX Chassis 2 M0 (EK1100)^EndX Chassis 2 M1 (EL3104); BoxAddr: 1072; Disabled: False
B693 = TerminalEL3104: EtherCAT Terminal EL3104 4-chn Analog Input; Rail: Middle; BoxNextB: NYQJTGJX; BoxPrev: BIXFLARP; PortPrevFull: 1072/B; PortPrevShort: B; Fullname: TIID^End X (EtherCAT)^EndX Link L0 (EK1501-0010)^EndX Link L6 (EK1521)^EndX Chassis 2 M0 (EK1100)^EndX Chassis 2 M2 (EL3104); BoxAddr: 1073; Disabled: False
B694 = TerminalEL3104: EtherCAT Terminal EL3104 4-chn Analog Input; Rail: Middle; BoxNextB: IPCSEAUE; BoxPrev: NWYIOJYV; PortPrevFull: 1073/B; PortPrevShort: B; Fullname: TIID^End X (EtherCAT)^EndX Link L0 (EK1501-0010)^EndX Link L6 (EK1521)^EndX Chassis 2 M0 (EK1100)^EndX Chassis 2 M3 (EL3104); BoxAddr: 1074; Disabled: False
B695 = TerminalEL3104: EtherCAT Terminal EL3104 4-chn Analog Input; Rail: Middle; BoxNextB: NHHAKPWM; BoxPrev: NYQJTGJX; PortPrevFull: 1074/B; PortPrevShort: B; Fullname: TIID^End X (EtherCAT)^EndX Link L0 (EK1501-0010)^EndX Link L6 (EK1521)^EndX Chassis 2 M0 (EK1100)^EndX Chassis 2 M4 (EL3104); BoxAddr: 1075; Disabled: False
B696 = TerminalEL4132: EtherCAT Terminal EL4132 2-chn Analog Ouput; Rail: Middle; BoxNextB: VNJSOXLY; BoxPrev: IPCSEAUE; PortPrevFull: 1075/B; PortPrevShort: B; Fullname: TIID^End X (EtherCAT)^EndX Link L0 (EK1501-0010)^EndX Link L6 (EK1521)^EndX Chassis 2 M0 (EK1100)^EndX Chassis 2 M5 (EL4132); BoxAddr: 1076; Disabled: False
B697 = TerminalEL9190: EtherCAT Terminal EL9190 Supply; BoxType: TerminalPassive; Rail: Middle; BoxNextB: OIORHXGN; BoxPrev: NHHAKPWM; PortPrevShort: B; Fullname: TIID^End X (EtherCAT)^EndX Link L0 (EK1501-0010)^EndX Link L6 (EK1521)^EndX Chassis 2 M0 (EK1100)^EndX Chassis 2 M6 (EL9190); Disabled: False
B698 = TerminalEL1124: EtherCAT Terminal EL1124 4-chn Digital Input; Rail: Middle; BoxNextB: EOCIDOFX; BoxPrev: VNJSOXLY; PortPrevFull: 1076/B; PortPrevShort: B; Fullname: TIID^End X (EtherCAT)^EndX Link L0 (EK1501-0010)^EndX Link L6 (EK1521)^EndX Chassis 2 M0 (EK1100)^EndX Chassis 2 M7 (EL1124); BoxAddr: 1077; Disabled: False
B699 = TerminalEL2124: EtherCAT Terminal EL2124 4-chn Digital Ouput; Rail: Middle; BoxNextB: OJUTNPIT; BoxPrev: OIORHXGN; PortPrevFull: 1077/B; PortPrevShort: B; Fullname: TIID^End X (EtherCAT)^EndX Link L0 (EK1501-0010)^EndX Link L6 (EK1521)^EndX Chassis 2 M0 (EK1100)^EndX Chassis 2 M8 (EL2124); BoxAddr: 1078; Disabled: False
B700 = TerminalEL3104: EtherCAT Terminal EL3104 4-chn Analog Input; Rail: Middle; BoxNextB: TUSASKOC; BoxPrev: EOCIDOFX; PortPrevFull: 1078/B; PortPrevShort: B; Fullname: TIID^End X (EtherCAT)^EndX Link L0 (EK1501-0010)^EndX Link L6 (EK1521)^EndX Chassis 2 M0 (EK1100)^EndX Chassis 2 M9 (EL3104); BoxAddr: 1079; Disabled: False
B701 = TerminalEL4134: EtherCAT Terminal EL4134 4-chn Analog Ouput; Rail: Middle; BoxNextB: QLJFCCIO; BoxPrev: OJUTNPIT; PortPrevFull: 1079/B; PortPrevShort: B; Fullname: TIID^End X (EtherCAT)^EndX Link L0 (EK1501-0010)^EndX Link L6 (EK1521)^EndX Chassis 2 M0 (EK1100)^EndX Chassis 2 M10 (EL4134); BoxAddr: 1080; Disabled: False
B702 = TerminalEL9410: EtherCAT Terminal EL9410 Power; Rail: Middle; BoxNextB: BTIXFGSC; BoxPrev: TUSASKOC; PortPrevFull: 1080/B; PortPrevShort: B; Fullname: TIID^End X (EtherCAT)^EndX Link L0 (EK1501-0010)^EndX Link L6 (EK1521)^EndX Chassis 2 M0 (EK1100)^EndX Chassis 2 M11 (EL9410); BoxAddr: 1081; Disabled: False
B703 = TerminalEL2124: EtherCAT Terminal EL2124 4-chn Digital Ouput; Rail: Middle; BoxNextB: PGMTRYNC; BoxPrev: QLJFCCIO; PortPrevFull: 1081/B; PortPrevShort: B; Fullname: TIID^End X (EtherCAT)^EndX Link L0 (EK1501-0010)^EndX Link L6 (EK1521)^EndX Chassis 2 M0 (EK1100)^EndX Chassis 2 M12 (EL2124); BoxAddr: 1082; Disabled: False
B704 = TerminalEL2124: EtherCAT Terminal EL2124 4-chn Digital Ouput; Rail: Middle; BoxNextB: DOXDMLCL; BoxPrev: BTIXFGSC; PortPrevFull: 1082/B; PortPrevShort: B; Fullname: TIID^End X (EtherCAT)^EndX Link L0 (EK1501-0010)^EndX Link L6 (EK1521)^EndX Chassis 2 M0 (EK1100)^EndX Chassis 2 M13 (EL2124); BoxAddr: 1083; Disabled: False
B705 = TerminalEL3104: EtherCAT Terminal EL3104 4-chn Analog Input; Rail: Middle; BoxNextB: CVWUFYIV; BoxPrev: PGMTRYNC; PortPrevFull: 1083/B; PortPrevShort: B; Fullname: TIID^End X (EtherCAT)^EndX Link L0 (EK1501-0010)^EndX Link L6 (EK1521)^EndX Chassis 2 M0 (EK1100)^EndX Chassis 2 M14 (EL3104); BoxAddr: 1084; Disabled: False
B706 = TerminalEL1124: EtherCAT Terminal EL1124 4-chn Digital Input; Rail: Middle; BoxNextB: MNDLFDRE; BoxPrev: DOXDMLCL; PortPrevFull: 1084/B; PortPrevShort: B; Fullname: TIID^End X (EtherCAT)^EndX Link L0 (EK1501-0010)^EndX Link L6 (EK1521)^EndX Chassis 2 M0 (EK1100)^EndX Chassis 2 M15 (EL1124); BoxAddr: 1085; Disabled: False
B707 = TerminalEL2124: EtherCAT Terminal EL2124 4-chn Digital Ouput; Rail: Middle; BoxNextB: LREIIPBC; BoxPrev: CVWUFYIV; PortPrevFull: 1085/B; PortPrevShort: B; Fullname: TIID^End X (EtherCAT)^EndX Link L0 (EK1501-0010)^EndX Link L6 (EK1521)^EndX Chassis 2 M0 (EK1100)^EndX Chassis 2 M16 (EL2124); BoxAddr: 1086; Disabled: False
B708 = TerminalEL3102: EtherCAT Terminal EL3102 2-chn Analog Input; Rail: Middle; BoxNextB: GNNCRQTC; BoxPrev: MNDLFDRE; PortPrevFull: 1086/B; PortPrevShort: B; Fullname: TIID^End X (EtherCAT)^EndX Link L0 (EK1501-0010)^EndX Link L6 (EK1521)^EndX Chassis 2 M0 (EK1100)^EndX Chassis 2 M17 (EL3102); BoxAddr: 1087; Disabled: False
B709 = TerminalEL9011: EtherCAT Terminal EL9011 End; BoxType: TerminalPassive; Rail: Middle; BoxPrev: LREIIPBC; PortPrevShort: B; Fullname: TIID^End X (EtherCAT)^EndX Link L0 (EK1501-0010)^EndX Link L6 (EK1521)^EndX Chassis 2 M0 (EK1100)^EndX Chassis 2 M18 (EL9011); Disabled: False
B710 = CouplerEK1100: EtherCAT Coupler; Rail: Right; BoxNextB: JFSFQGVU; BoxNextC: SGKBFUAI; BoxPrev: TQNAFHKI; PortPrevFull: 1071/C; PortPrevShort: C 'X2 Out'; Fullname: TIID^End X (EtherCAT)^EndX Link L0 (EK1501-0010)^EndX Link L6 (EK1521)^EndX Chassis 2 R0 (EK1100); BoxPorts: Junction; BoxAddr: 1088; Disabled: False
B711 = TerminalEL7332: EtherCAT Terminal EL7332 2-channel DC motor output stage 24 V DC, 1 A; Rail: Right; BoxNextB: LSICHVVT; BoxPrev: WVQJRASG; PortPrevFull: 1088/B; PortPrevShort: B; Fullname: TIID^End X (EtherCAT)^EndX Link L0 (EK1501-0010)^EndX Link L6 (EK1521)^EndX Chassis 2 R0 (EK1100)^EndX Chassis 2 R1 (EL7332); BoxAddr: 1089; PDO Outputs: 0x1604,0x1605,0x1606,0x1607; PDO Inputs: 0x1A04,0x1A06; Disabled: False
B712 = TerminalEL1094: EtherCAT Terminal EL1094 4-channel digital input terminal 24 V DC, switching to negative potential; Rail: Right; BoxNextB: GFMAIIMD; BoxPrev: JFSFQGVU; PortPrevFull: 1089/B; PortPrevShort: B; Fullname: TIID^End X (EtherCAT)^EndX Link L0 (EK1501-0010)^EndX Link L6 (EK1521)^EndX Chassis 2 R0 (EK1100)^EndX Chassis 2 R2 (EL1094); BoxAddr: 1090; Disabled: False
B713 = TerminalEL1094: EtherCAT Terminal EL1094 4-channel digital input terminal 24 V DC, switching to negative potential; Rail: Right; BoxNextB: DRTMPPSI; BoxPrev: LSICHVVT; PortPrevFull: 1090/B; PortPrevShort: B; Fullname: TIID^End X (EtherCAT)^EndX Link L0 (EK1501-0010)^EndX Link L6 (EK1521)^EndX Chassis 2 R0 (EK1100)^EndX Chassis 2 R3 (EL1094); BoxAddr: 1091; Disabled: False
B714 = TerminalEL2008: EtherCAT Terminal EL2008 8-channel digital output terminal 24 V DC, 0.5 A; Rail: Right; BoxNextB: DHNEHDUU; BoxPrev: GFMAIIMD; PortPrevFull: 1091/B; PortPrevShort: B; Fullname: TIID^End X (EtherCAT)^EndX Link L0 (EK1501-0010)^EndX Link L6 (EK1521)^EndX Chassis 2 R0 (EK1100)^EndX Chassis 2 R4 (EL2008); BoxAddr: 1092; Disabled: False
B715 = TerminalEL3102: EtherCAT Terminal EL3102 2-chn Analog Input; Rail: Right; BoxNextB: NWIBQMIU; BoxPrev: DRTMPPSI; PortPrevFull: 1092/B; PortPrevShort: B; Fullname: TIID^End X (EtherCAT)^EndX Link L0 (EK1501-0010)^EndX Link L6 (EK1521)^EndX Chassis 2 R0 (EK1100)^EndX Chassis 2 R5 (EL3102); BoxAddr: 1093; Disabled: False
B716 = TerminalEL1014: EtherCAT Terminal EL1014 4-channel digital input terminal 24 V DC; Rail: Right; BoxNextB: OIPRKTKK; BoxPrev: DHNEHDUU; PortPrevFull: 1093/B; PortPrevShort: B; Fullname: TIID^End X (EtherCAT)^EndX Link L0 (EK1501-0010)^EndX Link L6 (EK1521)^EndX Chassis 2 R0 (EK1100)^EndX Chassis 2 R6 (EL1014); BoxAddr: 1094; Disabled: False
B717 = TerminalEL3102: EtherCAT Terminal EL3102 2-chn Analog Input; Rail: Right; BoxNextB: MHLSGXJL; BoxPrev: NWIBQMIU; PortPrevFull: 1094/B; PortPrevShort: B; Fullname: TIID^End X (EtherCAT)^EndX Link L0 (EK1501-0010)^EndX Link L6 (EK1521)^EndX Chassis 2 R0 (EK1100)^EndX Chassis 2 R7 (EL3102); BoxAddr: 1095; Disabled: False
B718 = TerminalEL1014: EtherCAT Terminal EL1014 4-channel digital input terminal 24 V DC; Rail: Right; BoxNextB: QMAODVUS; BoxPrev: OIPRKTKK; PortPrevFull: 1095/B; PortPrevShort: B; Fullname: TIID^End X (EtherCAT)^EndX Link L0 (EK1501-0010)^EndX Link L6 (EK1521)^EndX Chassis 2 R0 (EK1100)^EndX Chassis 2 R8 (EL1014); BoxAddr: 1096; Disabled: False
B719 = TerminalEL1872InfoData: EtherCAT Terminal EL1872 16-channel digital input terminal 24 V DC; Rail: Right; BoxNextB: DAXEWBVP; BoxPrev: MHLSGXJL; PortPrevFull: 1096/B; PortPrevShort: B; Fullname: TIID^End X (EtherCAT)^EndX Link L0 (EK1501-0010)^EndX Link L6 (EK1521)^EndX Chassis 2 R0 (EK1100)^EndX Chassis 2 R9 (EL1872); BoxAddr: 1097; Disabled: False
B720 = TerminalEL2872: EtherCAT Terminal EL2872 16-channel digital output terminal 24 V DC; Rail: Right; BoxNextB: OQMJGCLE; BoxPrev: QMAODVUS; PortPrevFull: 1097/B; PortPrevShort: B; Fullname: TIID^End X (EtherCAT)^EndX Link L0 (EK1501-0010)^EndX Link L6 (EK1521)^EndX Chassis 2 R0 (EK1100)^EndX Chassis 2 R10 (EL2872); BoxAddr: 1098; Disabled: False
B721 = TerminalEL1872InfoData: EtherCAT Terminal EL1872 16-channel digital input terminal 24 V DC; Rail: Right; BoxNextB: GFDVTGNT; BoxPrev: DAXEWBVP; PortPrevFull: 1098/B; PortPrevShort: B; Fullname: TIID^End X (EtherCAT)^EndX Link L0 (EK1501-0010)^EndX Link L6 (EK1521)^EndX Chassis 2 R0 (EK1100)^EndX Chassis 2 R11 (EL1872); BoxAddr: 1099; Disabled: False
B722 = TerminalEL2872: EtherCAT Terminal EL2872 16-channel digital output terminal 24 V DC; Rail: Right; BoxNextB: XDUMHRNM; BoxPrev: OQMJGCLE; PortPrevFull: 1099/B; PortPrevShort: B; Fullname: TIID^End X (EtherCAT)^EndX Link L0 (EK1501-0010)^EndX Link L6 (EK1521)^EndX Chassis 2 R0 (EK1100)^EndX Chassis 2 R12 (EL2872); BoxAddr: 1100; Disabled: False
B723 = TerminalEL9011: EtherCAT Terminal EL9011 End; BoxType: TerminalPassive; Rail: Right; BoxPrev: GFDVTGNT; PortPrevShort: B; Fullname: TIID^End X (EtherCAT)^EndX Link L0 (EK1501-0010)^EndX Link L6 (EK1521)^EndX Chassis 2 R0 (EK1100)^EndX Chassis 2 R13 (EL9011); Disabled: False
B896#1 = TerminalEL3202-0010: EtherCAT Terminal EL3202-0010 2-chn Temperature Input; Disabled: False
B996#1 = TerminalEL1124: EtherCAT Terminal EL1124 4-chn Digital Input; Disabled: False
B997#1 = TerminalEL2124: EtherCAT Terminal EL2124 4-chn Digital Ouput; Disabled: False
B998#1 = TerminalEL3102: EtherCAT Terminal EL3102 2-chn Analog Input; Disabled: False
B999#1 = TerminalEL9190: EtherCAT Terminal EL9190 Supply; BoxType: TerminalPassive; Rail: Left; Disabled: False
V97 = HartmannSource_HartmannSourceEndInStruct: HartmannSourceEndInStruct; BoxType: Variable; Instance: H1TcsEndX Instance; PLC: H1TcsEndX; Task: TcsEStd
V98 = HartmannSource_HartmannSourceEndOutStruct: HartmannSourceEndOutStruct; BoxType: Variable; Task: TcsEStd; PLC: H1TcsEndX; Instance: H1TcsEndX Instance
V400 V401 = Demodulator_DemodulatorOutStruct: DemodulatorOutStruct; BoxType: Variable; Instance: H1IscEndX Instance; PLC: H1IscEndX; Task: IscEStd
V402 V403 = Demodulator_DemodulatorInStructSign: DemodulatorInStruct; BoxType: Variable; Instance: H1IscEndX Instance; PLC: H1IscEndX; Task: IscEStd
V404 V405 = Demodulator_DemodulatorInStructOk: DemodulatorInStruct; BoxType: Variable; Instance: H1IscEndX Instance; PLC: H1IscEndX; Task: IscEStd
V488 V489 = Picomotor_PicomotorInStruct: PicomotorInStruct; BoxType: Variable; Instance: H1AuxEndX Instance; PLC: H1AuxEndX; Task: AuxEStd
V542 = ALSLaser_ALSLaserInStruct: ALSLaserInStruct; BoxType: Variable; Instance: H1IscEndX Instance; PLC: H1IscEndX; Task: IscEStd
V543-V546 = RFAmplifier_RFAmplifierInStruct: RFAmplifierInStruct; BoxType: Variable; Instance: H1IscEndX Instance; PLC: H1IscEndX; Task: IscEStd
V547 = RingHeater_RingHeaterInStruct: RingHeaterInStruct; BoxType: Variable; Instance: H1TcsEndX Instance; PLC: H1TcsEndX; Task: TcsEStd
V548 = RingHeater_RingHeaterOutStruct: RingHeaterOutStruct; BoxType: Variable; Instance: H1TcsEndX Instance; PLC: H1TcsEndX; Task: TcsEStd
V549 = HartmannSensor_HartmannSensorEndOutStruct: HartmannSensorOutStruct; BoxType: Variable; Instance: H1TcsEndX Instance; PLC: H1TcsEndX; Task: TcsEStd
V550 V551 = PZTMirror_PZTMirrorInStruct: PZTMirrorInStruct; BoxType: Variable; Instance: H1IscEndX Instance; PLC: H1IscEndX; Task: IscEStd
V552-V555 V565 V566 V569 V570 = DCPower_DCPowerInStruct: DCPowerInStruct; BoxType: Variable; Instance: H1IscEndX Instance; PLC: H1IscEndX; Task: IscEStd
V556 = ALSLaser_ALSLaserOutStruct: ALSLaserOutStruct; BoxType: Variable; Instance: H1IscEndX Instance; PLC: H1IscEndX; Task: IscEStd
V557 = Auxiliary_AuxiliaryInStruct: AuxiliaryInStruct; BoxType: Variable; Instance: H1IscEndX Instance; PLC: H1IscEndX; Task: IscEStd
V558 = Auxiliary_AuxiliaryOutStruct: AuxiliaryOutStruct; BoxType: Variable; Instance: H1IscEndX Instance; PLC: H1IscEndX; Task: IscEStd
V559 = RTCommunication_ReceiveFromRtInStruct: ReceiveFromRtInStruct; BoxType: Variable; Instance: H1IscEndX Instance; PLC: H1IscEndX; Task: IscEStd
V560 = RTCommunication_SendToRtOutStruct: SendToRtOutStruct; BoxType: Variable; Instance: H1IscEndX Instance; PLC: H1IscEndX; Task: IscEStd
V561-V564 = DCPower_DCPowerOutStruct: DCPowerOutStruct; BoxType: Variable; Instance: H1IscEndX Instance; PLC: H1IscEndX; Task: IscEStd
V571 = DCPower_DCPowerOutStructLegacy: DCPowerOutStruct; BoxType: Variable; Instance: H1IscEndX Instance; PLC: H1IscEndX; Task: IscEStd
V572 = DCPower_DCPowerInStructLegacy: DCPowerInStruct; BoxType: Variable; Instance: H1IscEndX Instance; PLC: H1IscEndX; Task: IscEStd
V573 V576 = Picomotor_PicomotorFastInStruct: PicomotorFastInStruct; BoxType: Variable; Instance: H1AuxEndX Instance; PLC: H1AuxEndX; Task: AuxEFast
V574 V577 = Picomotor_PicomotorOutStruct: PicomotorOutStruct; BoxType: Variable; Instance: H1AuxEndX Instance; PLC: H1AuxEndX; Task: AuxEStd
V575 V578 = Picomotor_PicomotorFastOutStruct: PicomotorFastOutStruct; BoxType: Variable; Instance: H1AuxEndX Instance; PLC: H1AuxEndX; Task: AuxEFast
V579 = BeamDiverter_BeamDiverterInStruct: BeamDiverterInStruct; BoxType: Variable; Instance: H1AuxEndX Instance; PLC: H1AuxEndX; Task: AuxEStd
V580 = BeamDiverter_BeamDiverterOutStruct: BeamDiverterOutStruct; BoxType: Variable; Instance: H1AuxEndX Instance; PLC: H1AuxEndX; Task: AuxEStd
V581 V582 = ShutterControl_ShutterControlInStruct: ShutterControlInStruct; BoxType: Variable; Instance: H1AuxEndX Instance; PLC: H1AuxEndX; Task: AuxEStd
V583 V721 = ShutterControl_ShutterControlOutStruct: ShutterControlOutStruct; BoxType: Variable; Instance: H1AuxEndX Instance; PLC: H1AuxEndX; Task: AuxEStd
